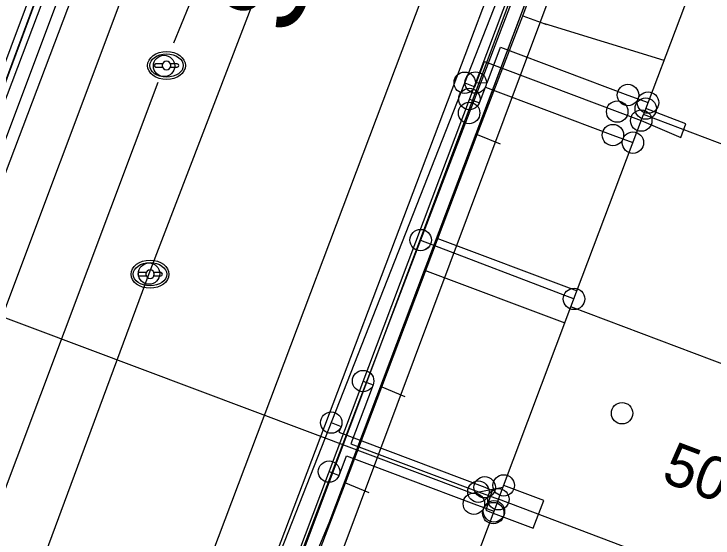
# Model space of a CAD drawing. Extents: x 192672 to 192910, y 446344 to 446512.
# Drawn here: x 192756.71 to 192773.02, y 446443.08 to 446455.32 of the extents above; entities that cross this region are included whole.
import ezdxf

# ---------------------------------------------------------------- set-up
doc = ezdxf.new("R2010")
doc.units = 0
for name, color, linetype in [('B-OI-KL-()_MANTELBUIS_WATER-G', 7, 'Continuous'), ('B-OI-KL-()_OVERIG_RIOOLVRIJVERVAL-S', 7, 'Continuous'), ('B-OI-KL-BUISLEIDING_OLIEGASCHEMICALIEN_GASLAGEDRUK-G', 7, 'Continuous'), ('B-OI-KL-DATA-G', 7, 'Continuous'), ('B-OI-KL-DATA_GTWP-S', 7, 'Continuous'), ('B-OI-KL-DATA_KABELBED-G', 7, 'Continuous'), ('B-OI-KL-DATA_MOF-S', 7, 'Continuous'), ('B-OI-KL-ET_LS-G', 7, 'Continuous'), ('B-OI-KL-ET_LS_DELIVERYPOINT-S', 7, 'Continuous'), ('B-OI-KL-ET_LS_MOF-S', 7, 'Continuous'), ('B-OI-KL-GAS_LD_AFTAKZADEL-S', 7, 'Continuous'), ('B-OI-KL-GAS_LD_DELIVERYPOINT-S', 7, 'Continuous'), ('B-OI-KL-GAS_LD_OVERGANGSSTUK-S', 7, 'Continuous'), ('B-OI-KL-WATER-G', 7, 'Continuous'), ('B-OI-RI-RIOOLVRIJVERVAL-G', 7, 'Continuous'), ('Default', 7, 'Continuous'), ('huisnummerreeks BGT', 7, 'Continuous'), ('inspectie-   rioolput', 7, 'Continuous'), ('kant open verharding', 7, 'Continuous'), ('kant verharding', 7, 'Continuous'), ('pand op maaiveld vlak', 7, 'Continuous'), ('straatnaam', 7, 'Continuous')]:
    doc.layers.add(name, color=color, linetype=linetype)

# ---------------------------------------------------------------- blocks, each defined once
blk = doc.blocks.new('B-OI-KL-GAS_LD_AFTAKZADEL-S')
at = {"layer": 'Default'}
blk.add_circle((0, 0), 0.25, dxfattribs=at)
blk = doc.blocks.new('B-OI-KL-GAS_LD_DELIVERYPOINT-S')
at = {"layer": 'Default'}
blk.add_circle((0, 0), 0.25, dxfattribs=at)
blk = doc.blocks.new('B-OI-KL-GAS_LD_OVERGANGSSTUK-S')
at = {"layer": 'Default'}
blk.add_circle((0, 0), 0.25, dxfattribs=at)
blk = doc.blocks.new('B-OI-KL-ET_LS_DELIVERYPOINT-S')
at = {"layer": 'Default'}
blk.add_circle((0, 0), 0.25, dxfattribs=at)
blk = doc.blocks.new('B-OI-KL-ET_LS_MOF-S')
at = {"layer": 'Default'}
blk.add_circle((0, 0), 0.25, dxfattribs=at)
blk = doc.blocks.new('B-OI-KL-()_OVERIG_RIOOLVRIJVERVAL-S')
at = {"layer": 'Default'}
blk.add_circle((0, 0), 0.25, dxfattribs=at)
blk = doc.blocks.new('B-OI-KL-DATA_GTWP-S')
at = {"layer": 'Default'}
blk.add_circle((0, 0), 0.25, dxfattribs=at)
blk = doc.blocks.new('B-OI-KL-DATA_MOF-S')
at = {"layer": 'Default'}
blk.add_circle((0, 0), 0.25, dxfattribs=at)

msp = doc.modelspace()

# ---------------------------------------------------------------- linework, layer by layer
at = {"layer": 'B-OI-KL-()_MANTELBUIS_WATER-G'}
msp.add_lwpolyline([(192767.826, 446444.213), (192768.121, 446444.271)], dxfattribs=at)
at = {"layer": 'B-OI-KL-BUISLEIDING_OLIEGASCHEMICALIEN_GASLAGEDRUK-G'}
for points in [[(192808.99, 446509.756), (192805.748, 446508.276), (192801.187, 446506.24), (192794.261, 446502.995), (192789.059, 446500.595), (192784.967, 446498.672), (192784.158, 446498.207), (192778.689, 446484.216), (192775.51, 446475.031), (192756.472, 446424.494), (192754.598, 446419.974), (192751.089, 446410.462)], [(192770.261, 446499.113), (192771.393, 446496.803), (192772.556, 446494.554), (192770.877, 446489.886), (192758.67, 446457.345), (192745.084, 446421.436), (192742.217, 446413.618)], [(192767.483, 446453.723), (192767.749, 446453.719), (192768.063, 446454.552), (192771.038, 446453.431)], [(192767.338, 446453.338), (192767.572, 446453.25), (192767.71, 446453.616), (192770.686, 446452.495)], [(192771.038, 446453.431), (192771.506, 446453.255)], [(192770.686, 446452.495), (192771.153, 446452.319)], [(192764.857, 446446.751), (192765.091, 446446.663), (192764.573, 446445.288), (192767.547, 446444.167)], [(192764.061, 446444.637), (192764.295, 446444.549), (192764.467, 446445.007), (192767.441, 446443.886)], [(192767.547, 446444.167), (192768.015, 446443.99)], [(192767.441, 446443.886), (192767.909, 446443.709)]]:
    msp.add_lwpolyline(points, dxfattribs=at)
at = {"layer": 'B-OI-KL-DATA-G'}
for points in [[(192745.236, 446436.264), (192745.276, 446436.371), (192749.491, 446434.791), (192749.794, 446435.599), (192768.74, 446486.807), (192770.369, 446486.306), (192778.924, 446483.081), (192784.343, 446497.176), (192794.941, 446502.078), (192811.396, 446509.756)], [(192757.844, 446425.655), (192756.715, 446426.08), (192759.12, 446432.478), (192750.822, 446435.215), (192749.794, 446435.599), (192768.74, 446486.807), (192770.369, 446486.306), (192778.924, 446483.081), (192784.343, 446497.176), (192794.941, 446502.078), (192811.396, 446509.756)], [(192757.844, 446425.655), (192756.715, 446426.08), (192759.12, 446432.478), (192750.822, 446435.215), (192749.794, 446435.599), (192768.74, 446486.807), (192770.369, 446486.306), (192778.924, 446483.081), (192784.343, 446497.176), (192794.941, 446502.078), (192811.396, 446509.756)], [(192757.844, 446425.655), (192756.715, 446426.08), (192759.12, 446432.478), (192750.822, 446435.215), (192749.794, 446435.599), (192768.74, 446486.807), (192770.369, 446486.306), (192778.924, 446483.081), (192784.343, 446497.176), (192794.941, 446502.078), (192811.396, 446509.756)], [(192757.844, 446425.655), (192756.715, 446426.08), (192759.12, 446432.478), (192750.822, 446435.215), (192749.794, 446435.599), (192768.74, 446486.807), (192770.369, 446486.306), (192778.924, 446483.081), (192784.343, 446497.176), (192794.941, 446502.078), (192811.396, 446509.756)], [(192757.844, 446425.655), (192756.715, 446426.08), (192759.12, 446432.478), (192750.822, 446435.215), (192749.794, 446435.599), (192768.74, 446486.807), (192770.369, 446486.306), (192778.924, 446483.081), (192784.343, 446497.176), (192794.941, 446502.078), (192811.396, 446509.756)], [(192757.844, 446425.655), (192756.715, 446426.08), (192759.12, 446432.478), (192750.822, 446435.215), (192749.794, 446435.599), (192768.74, 446486.807), (192770.369, 446486.306), (192778.924, 446483.081), (192784.343, 446497.176), (192794.941, 446502.078), (192811.396, 446509.756)], [(192757.844, 446425.655), (192756.715, 446426.08), (192759.12, 446432.478), (192750.822, 446435.215), (192749.794, 446435.599), (192768.74, 446486.807), (192770.369, 446486.306), (192778.924, 446483.081), (192784.343, 446497.176), (192794.941, 446502.078), (192811.396, 446509.756)], [(192768.74, 446486.807), (192749.794, 446435.599), (192742.072, 446415.039), (192739.06, 446406.841), (192720.2, 446413.77), (192719.012, 446414.118), (192696.077, 446422.823), (192683.193, 446427.673), (192678.122, 446429.261), (192675.743, 446430.156)], [(192768.74, 446486.807), (192749.794, 446435.599), (192742.072, 446415.039), (192739.06, 446406.841), (192738.917, 446406.249), (192738.75, 446405.758), (192738.438, 446405.088), (192738.002, 446404.406), (192737.543, 446403.858), (192737.067, 446403.408), (192736.56, 446403.025), (192736.06, 446402.723), (192733.684, 446396.245), (192734.518, 446394.712), (192730.316, 446383.423), (192727.316, 446375.697), (192722.899, 446364.033), (192722.458, 446362.715), (192718.077, 446351.086), (192716.68, 446347.404), (192715.968, 446345.556)], [(192768.74, 446486.807), (192749.794, 446435.599), (192742.072, 446415.039), (192739.06, 446406.841), (192738.917, 446406.249), (192738.75, 446405.758), (192738.438, 446405.088), (192738.002, 446404.406), (192737.543, 446403.858), (192737.067, 446403.408), (192736.56, 446403.025), (192736.06, 446402.723), (192733.684, 446396.245), (192734.518, 446394.712), (192730.316, 446383.423), (192727.316, 446375.697), (192722.899, 446364.033), (192722.458, 446362.715), (192718.077, 446351.086), (192716.68, 446347.404), (192715.968, 446345.556)], [(192768.74, 446486.807), (192749.794, 446435.599), (192742.072, 446415.039), (192739.06, 446406.841), (192738.917, 446406.249), (192738.75, 446405.758), (192738.438, 446405.088), (192738.002, 446404.406), (192737.543, 446403.858), (192737.067, 446403.408), (192736.56, 446403.025), (192736.06, 446402.723), (192733.684, 446396.245), (192734.518, 446394.712), (192730.316, 446383.423), (192727.316, 446375.697), (192722.899, 446364.033), (192722.458, 446362.715), (192718.077, 446351.086), (192716.68, 446347.404), (192715.968, 446345.556)], [(192768.74, 446486.807), (192749.794, 446435.599), (192742.072, 446415.039), (192739.06, 446406.841), (192738.917, 446406.249), (192738.75, 446405.758), (192738.438, 446405.088), (192738.002, 446404.406), (192737.543, 446403.858), (192737.067, 446403.408), (192736.56, 446403.025), (192736.06, 446402.723), (192733.684, 446396.245), (192734.518, 446394.712), (192730.316, 446383.423), (192727.316, 446375.697), (192722.899, 446364.033), (192722.458, 446362.715), (192718.077, 446351.086), (192716.68, 446347.404), (192715.968, 446345.556)], [(192768.74, 446486.807), (192749.794, 446435.599), (192742.072, 446415.039), (192739.06, 446406.841), (192738.917, 446406.249), (192738.75, 446405.758), (192738.438, 446405.088), (192738.002, 446404.406), (192737.543, 446403.858), (192737.067, 446403.408), (192736.56, 446403.025), (192736.06, 446402.723), (192733.684, 446396.245), (192734.518, 446394.712), (192730.316, 446383.423), (192727.316, 446375.697), (192722.899, 446364.033), (192722.458, 446362.715), (192718.077, 446351.086), (192716.68, 446347.404), (192715.968, 446345.556)], [(192768.74, 446486.807), (192749.794, 446435.599), (192742.072, 446415.039), (192739.06, 446406.841), (192738.917, 446406.249), (192738.75, 446405.758), (192738.438, 446405.088), (192738.002, 446404.406), (192737.543, 446403.858), (192737.067, 446403.408), (192736.56, 446403.025), (192736.06, 446402.723), (192733.684, 446396.245), (192734.518, 446394.712), (192730.316, 446383.423), (192727.316, 446375.697), (192722.899, 446364.033), (192722.458, 446362.715), (192718.077, 446351.086), (192716.68, 446347.404), (192715.968, 446345.556)], [(192768.74, 446486.807), (192749.794, 446435.599), (192742.072, 446415.039), (192739.06, 446406.841), (192738.917, 446406.249), (192738.75, 446405.758), (192738.438, 446405.088), (192738.002, 446404.406), (192737.543, 446403.858), (192737.067, 446403.408), (192736.56, 446403.025), (192736.06, 446402.723), (192733.684, 446396.245), (192734.518, 446394.712), (192730.316, 446383.423), (192727.316, 446375.697), (192722.899, 446364.033), (192722.458, 446362.715), (192718.077, 446351.086), (192716.68, 446347.404), (192715.968, 446345.556)], [(192768.74, 446486.807), (192749.794, 446435.599), (192742.072, 446415.039), (192739.06, 446406.841), (192738.917, 446406.249), (192738.75, 446405.758), (192738.438, 446405.088), (192738.002, 446404.406), (192737.543, 446403.858), (192737.067, 446403.408), (192736.56, 446403.025), (192736.06, 446402.723), (192733.684, 446396.245), (192734.518, 446394.712), (192730.316, 446383.423), (192727.316, 446375.697), (192722.899, 446364.033), (192722.458, 446362.715), (192718.077, 446351.086), (192716.68, 446347.404), (192715.968, 446345.556)], [(192768.74, 446486.807), (192749.794, 446435.599), (192742.072, 446415.039), (192739.06, 446406.841), (192738.917, 446406.249), (192738.75, 446405.758), (192738.438, 446405.088), (192738.002, 446404.406), (192737.543, 446403.858), (192737.067, 446403.408), (192736.56, 446403.025), (192736.06, 446402.723), (192733.684, 446396.245), (192734.518, 446394.712), (192730.316, 446383.423), (192727.316, 446375.697), (192722.899, 446364.033), (192722.458, 446362.715), (192718.077, 446351.086), (192716.68, 446347.404), (192715.968, 446345.556)], [(192768.74, 446486.807), (192749.794, 446435.599), (192742.072, 446415.039), (192739.06, 446406.841), (192738.917, 446406.249), (192738.75, 446405.758), (192738.438, 446405.088), (192738.002, 446404.406), (192737.543, 446403.858), (192737.067, 446403.408), (192736.56, 446403.025), (192736.06, 446402.723), (192733.684, 446396.245), (192734.518, 446394.712), (192730.316, 446383.423), (192727.316, 446375.697), (192722.899, 446364.033), (192722.458, 446362.715), (192718.077, 446351.086), (192716.68, 446347.404), (192715.968, 446345.556)], [(192768.74, 446486.807), (192749.794, 446435.599), (192742.072, 446415.039), (192739.06, 446406.841), (192738.917, 446406.249), (192738.75, 446405.758), (192738.438, 446405.088), (192738.002, 446404.406), (192737.543, 446403.858), (192737.067, 446403.408), (192736.56, 446403.025), (192736.06, 446402.723), (192733.684, 446396.245), (192734.518, 446394.712), (192730.316, 446383.423), (192727.316, 446375.697), (192722.899, 446364.033), (192722.458, 446362.715), (192718.077, 446351.086), (192716.68, 446347.404), (192715.968, 446345.556)], [(192768.74, 446486.807), (192749.794, 446435.599), (192742.072, 446415.039), (192739.06, 446406.841), (192738.917, 446406.249), (192738.75, 446405.758), (192738.438, 446405.088), (192738.002, 446404.406), (192737.543, 446403.858), (192737.067, 446403.408), (192736.56, 446403.025), (192736.06, 446402.723), (192733.684, 446396.245), (192734.518, 446394.712), (192730.316, 446383.423), (192727.316, 446375.697), (192722.899, 446364.033), (192722.458, 446362.715), (192718.077, 446351.086), (192716.68, 446347.404), (192715.968, 446345.556)], [(192768.74, 446486.807), (192749.794, 446435.599), (192742.072, 446415.039), (192739.06, 446406.841), (192738.917, 446406.249), (192738.75, 446405.758), (192738.438, 446405.088), (192738.002, 446404.406), (192737.543, 446403.858), (192737.067, 446403.408), (192736.56, 446403.025), (192736.06, 446402.723), (192733.684, 446396.245), (192734.518, 446394.712), (192730.316, 446383.423), (192727.316, 446375.697), (192722.899, 446364.033), (192722.458, 446362.715), (192718.077, 446351.086), (192716.68, 446347.404), (192715.968, 446345.556)], [(192768.74, 446486.807), (192749.794, 446435.599), (192742.072, 446415.039), (192739.06, 446406.841), (192738.917, 446406.249), (192738.75, 446405.758), (192738.438, 446405.088), (192738.002, 446404.406), (192737.543, 446403.858), (192737.067, 446403.408), (192736.56, 446403.025), (192736.06, 446402.723), (192733.684, 446396.245), (192734.518, 446394.712), (192730.316, 446383.423), (192727.316, 446375.697), (192722.899, 446364.033), (192722.458, 446362.715), (192718.077, 446351.086), (192716.68, 446347.404), (192715.968, 446345.556)], [(192768.74, 446486.807), (192749.794, 446435.599), (192742.072, 446415.039), (192739.06, 446406.841), (192738.917, 446406.249), (192738.75, 446405.758), (192738.438, 446405.088), (192738.002, 446404.406), (192737.543, 446403.858), (192737.067, 446403.408), (192736.56, 446403.025), (192736.06, 446402.723), (192733.684, 446396.245), (192734.518, 446394.712), (192730.316, 446383.423), (192727.316, 446375.697), (192722.899, 446364.033), (192722.458, 446362.715), (192718.077, 446351.086), (192716.68, 446347.404), (192715.968, 446345.556)], [(192733.785, 446392.743), (192734.518, 446394.712), (192733.684, 446396.245), (192736.06, 446402.723), (192736.56, 446403.025), (192737.067, 446403.408), (192737.543, 446403.858), (192738.002, 446404.406), (192738.438, 446405.088), (192738.75, 446405.758), (192738.917, 446406.249), (192739.06, 446406.841), (192742.072, 446415.039), (192749.794, 446435.599), (192768.74, 446486.807)], [(192768.74, 446486.807), (192749.794, 446435.599), (192749.491, 446434.791), (192745.276, 446436.371), (192745.236, 446436.264)], [(192757.844, 446425.655), (192756.715, 446426.08), (192759.12, 446432.478), (192750.822, 446435.215), (192749.794, 446435.599), (192768.74, 446486.807)], [(192757.844, 446425.655), (192757.559, 446425.762), (192762.265, 446439.137), (192764.067, 446443.44), (192769.642, 446458.233), (192775.813, 446474.194), (192776.451, 446473.954)], [(192757.844, 446425.655), (192757.559, 446425.762), (192762.265, 446439.137), (192764.067, 446443.44), (192769.642, 446458.233), (192774.396, 446470.528), (192775.064, 446470.277)], [(192745.236, 446436.264), (192745.276, 446436.371), (192749.491, 446434.791), (192749.794, 446435.599), (192760.694, 446465.06)], [(192768.581, 446455.281), (192770.176, 446459.553), (192771.392, 446462.778)], [(192745.236, 446436.264), (192745.276, 446436.371), (192749.491, 446434.791), (192749.794, 446435.599), (192759.161, 446460.917)], [(192757.844, 446425.655), (192757.559, 446425.762), (192762.265, 446439.137), (192764.067, 446443.44), (192769.642, 446458.233), (192770.479, 446460.397), (192771.235, 446460.112)], [(192757.844, 446425.655), (192757.559, 446425.762), (192762.265, 446439.137), (192764.067, 446443.44), (192769.642, 446458.233), (192772.918, 446456.997)], [(192745.236, 446436.264), (192745.276, 446436.371), (192749.491, 446434.791), (192749.794, 446435.599), (192757.561, 446456.593)], [(192767.516, 446452.511), (192768.581, 446455.281)], [(192768.581, 446455.281), (192769.097, 446455.091)], [(192771.88, 446454.24), (192769.097, 446455.091)], [(192769.097, 446455.091), (192769.126, 446455.08)], [(192765.29, 446446.613), (192767.516, 446452.511)], [(192767.516, 446452.511), (192768.054, 446452.292)], [(192757.844, 446425.655), (192757.559, 446425.762), (192762.265, 446439.137), (192764.067, 446443.44), (192766.573, 446450.09), (192769.849, 446448.856)], [(192757.844, 446425.655), (192757.559, 446425.762), (192762.265, 446439.137), (192764.067, 446443.44), (192766.291, 446449.342), (192769.567, 446448.108)], [(192764.443, 446444.377), (192765.29, 446446.613)], [(192765.29, 446446.613), (192765.828, 446446.389)], [(192761.261, 446436.309), (192762.488, 446439.513), (192763.052, 446440.678), (192763.221, 446441.171), (192764.443, 446444.377)], [(192764.443, 446444.377), (192764.988, 446444.146)]]:
    msp.add_lwpolyline(points, dxfattribs=at)
at = {"layer": 'B-OI-KL-DATA_KABELBED-G'}
for points in [[(192781.5, 446489.931), (192778.594, 446482.476), (192777.525, 446479.682), (192775.942, 446475.544), (192774.287, 446471.219), (192774.071, 446470.654), (192771.264, 446463.317), (192769.537, 446458.803), (192769.421, 446458.498), (192766.199, 446450.043), (192761.064, 446436.566), (192759.105, 446431.427), (192758.318, 446429.36), (192752.08, 446412.145), (192751.738, 446411.209)], [(192741.713, 446414.036), (192744.844, 446423.02), (192745.937, 446425.921), (192747.211, 446429.306), (192749.226, 446434.655), (192749.571, 446435.71), (192751.005, 446439.535), (192753.868, 446447.173), (192756.275, 446453.596), (192757.334, 446456.42), (192758.244, 446458.849)], [(192766.573, 446450.09), (192769.642, 446458.233)], [(192755.845, 446451.955), (192757.561, 446456.593)], [(192766.199, 446450.043), (192769.779, 446448.67)], [(192766.291, 446449.342), (192766.573, 446450.09)], [(192766.573, 446450.09), (192769.849, 446448.856)], [(192762.662, 446440.084), (192764.067, 446443.44), (192766.291, 446449.342)], [(192766.291, 446449.342), (192769.567, 446448.108)]]:
    msp.add_lwpolyline(points, dxfattribs=at)
at = {"layer": 'B-OI-KL-ET_LS-G'}
for points in [[(192737.952, 446406.43), (192738.358, 446406.675), (192738.717, 446406.983), (192739.022, 446407.347), (192739.262, 446407.755), (192739.381, 446408.001), (192760.347, 446463.479), (192768.676, 446485.881)], [(192751.683, 446410.693), (192751.297, 446411.193), (192751.249, 446411.263), (192751.183, 446411.41), (192751.151, 446411.568), (192751.154, 446411.72), (192751.195, 446411.884), (192761.82, 446439.945), (192769.713, 446460.045), (192776.093, 446476.975), (192777.923, 446482.086)], [(192769.108, 446460.374), (192769.235, 446460.249), (192769.933, 446460.043), (192761.858, 446438.501), (192761.067, 446436.302), (192760.076, 446436.613), (192759.938, 446436.632)], [(192767.228, 446453.717), (192767.461, 446453.626), (192767.691, 446454.212), (192770.786, 446453.045)], [(192771.347, 446452.834), (192772.272, 446452.439), (192772.389, 446452.761), (192771.453, 446453.114)], [(192770.786, 446453.045), (192771.347, 446452.834)], [(192764.112, 446445.781), (192764.345, 446445.69), (192764.291, 446445.554), (192767.694, 446444.271)], [(192767.893, 446443.667), (192768.829, 446443.314), (192769.073, 446443.961), (192768.137, 446444.313)], [(192767.694, 446444.271), (192767.867, 446444.197), (192767.72, 446443.732), (192767.893, 446443.667)]]:
    msp.add_lwpolyline(points, dxfattribs=at)
at = {"layer": 'B-OI-KL-WATER-G'}
msp.add_lwpolyline([(192754.259, 446449.069), (192754.494, 446448.983), (192767.404, 446444.129), (192768.121, 446444.271)], dxfattribs=at)
at = {"layer": 'B-OI-RI-RIOOLVRIJVERVAL-G'}
for points in [[(192759.86, 446449.26), (192779.05, 446499.28)], [(192760.441, 446454.647), (192761.511, 446457.277)], [(192760.065, 446453.723), (192752.396, 446433.312), (192756.051, 446431.824), (192756.134, 446431.668), (192755.956, 446431.084), (192756.039, 446430.928), (192756.54, 446430.74)], [(192740.63, 446397.31), (192759.86, 446449.26)]]:
    msp.add_lwpolyline(points, dxfattribs=at)
at = {"layer": 'inspectie-   rioolput'}
for p, q in [((192760.175, 446454.158), (192760.018, 446454.158)), ((192760.018, 446454.083), (192760.175, 446454.083)), ((192760.518, 446454.158), (192760.361, 446454.158)), ((192760.361, 446454.083), (192760.518, 446454.083)), ((192759.79, 446449.284), (192759.633, 446449.284)), ((192759.633, 446449.209), (192759.79, 446449.209)), ((192760.133, 446449.284), (192759.976, 446449.284)), ((192759.976, 446449.209), (192760.133, 446449.209))]:
    msp.add_line(p, q, dxfattribs=at)
for centre, radius, start, end in [((192760.018, 446454.12), 0.0375, 90, 270), ((192760.268, 446454.12), 0.1, 0, 180), ((192760.268, 446454.12), 0.1, 157.9757, 180), ((192760.268, 446454.12), 0.1, 180, 202.0243), ((192760.268, 446454.12), 0.1, 180, 0), ((192760.268, 446454.12), 0.1, 0, 22.0243), ((192760.268, 446454.12), 0.1, 337.9757, 0), ((192760.518, 446454.12), 0.0375, 270, 90), ((192759.633, 446449.246), 0.0375, 90, 270), ((192759.883, 446449.246), 0.1, 0, 180), ((192759.883, 446449.246), 0.1, 157.9757, 180), ((192759.883, 446449.246), 0.1, 180, 202.0243), ((192759.883, 446449.246), 0.1, 180, 0), ((192759.883, 446449.246), 0.1, 0, 22.0243), ((192759.883, 446449.246), 0.1, 337.9757, 0), ((192760.133, 446449.246), 0.0375, 270, 90)]:
    msp.add_arc(centre, radius, start, end, dxfattribs=at)
for centre, major_axis, ratio in [((192760.268, 446454.12), (-0.442, 0), 0.73911), ((192760.268, 446454.12), (-0.392, 0), 0.689655), ((192759.883, 446449.246), (-0.442, 0), 0.73911), ((192759.883, 446449.246), (-0.392, 0), 0.689655)]:
    msp.add_ellipse(centre, major_axis=major_axis, ratio=ratio, dxfattribs=at)
at = {"layer": 'kant open verharding'}
msp.add_lwpolyline([(192763.131, 446439.452), (192770.245, 446458.483), (192770.698, 446459.694), (192771.023, 446459.551)], dxfattribs=at)
at = {"layer": 'kant verharding'}
for p, q in [((192759.42, 446437.63), (192767.733, 446459.699)), ((192751.413, 446438.852), (192759.133, 446459.368)), ((192760.585, 446459.343), (192752.554, 446437.93))]:
    msp.add_line(p, q, dxfattribs=at)
msp.add_lwpolyline([(192768.035, 446459.06), (192768.878, 446458.723), (192760.872, 446437.554), (192760.052, 446437.884)], dxfattribs=at)
at = {"layer": 'pand op maaiveld vlak'}
for p, q in [((192769.708, 446448.482), (192771.4, 446452.974)), ((192782.591, 446448.755), (192771.4, 446452.974)), ((192768.015, 446443.99), (192769.708, 446448.482)), ((192780.892, 446444.248), (192769.708, 446448.482)), ((192779.205, 446439.772), (192768.015, 446443.99))]:
    msp.add_line(p, q, dxfattribs=at)
for points in [[(192782.591, 446448.755), (192784.284, 446453.247), (192780.202, 446454.786), (192773.094, 446457.465), (192771.4, 446452.974)], [(192768.015, 446443.99), (192766.321, 446439.499), (192773.437, 446436.816), (192777.512, 446435.28), (192779.205, 446439.772)]]:
    msp.add_lwpolyline(points, dxfattribs=at)

# ---------------------------------------------------------------- block references
at = {"layer": 'B-OI-KL-()_OVERIG_RIOOLVRIJVERVAL-S'}
for p in [(192760.21, 446454.11), (192759.86, 446449.26)]:
    msp.add_blockref('B-OI-KL-()_OVERIG_RIOOLVRIJVERVAL-S', p, dxfattribs=at)
at = {"layer": 'B-OI-KL-DATA_GTWP-S'}
for p in [(192766.199, 446450.042), (192769.779, 446448.67)]:
    msp.add_blockref('B-OI-KL-DATA_GTWP-S', p, dxfattribs=at)
at = {"layer": 'B-OI-KL-DATA_MOF-S'}
for p in [(192767.331, 446453.012), (192766.199, 446450.043), (192770.9, 446446)]:
    msp.add_blockref('B-OI-KL-DATA_MOF-S', p, dxfattribs=at)
at = {"layer": 'B-OI-KL-ET_LS_DELIVERYPOINT-S'}
for p in [(192771.453, 446453.114), (192771.347, 446452.834), (192768.137, 446444.313), (192767.893, 446443.667)]:
    msp.add_blockref('B-OI-KL-ET_LS_DELIVERYPOINT-S', p, dxfattribs=at)
at = {"layer": 'B-OI-KL-ET_LS_MOF-S'}
for p in [(192767.228, 446453.717), (192770.786, 446453.045), (192764.112, 446445.781), (192767.694, 446444.271)]:
    msp.add_blockref('B-OI-KL-ET_LS_MOF-S', p, dxfattribs=at)
at = {"layer": 'B-OI-KL-GAS_LD_AFTAKZADEL-S'}
for p in [(192767.483, 446453.723), (192767.338, 446453.338), (192764.857, 446446.751), (192764.061, 446444.637)]:
    msp.add_blockref('B-OI-KL-GAS_LD_AFTAKZADEL-S', p, dxfattribs=at)
at = {"layer": 'B-OI-KL-GAS_LD_DELIVERYPOINT-S'}
for p in [(192771.506, 446453.255), (192771.153, 446452.319), (192768.015, 446443.99), (192767.909, 446443.709)]:
    msp.add_blockref('B-OI-KL-GAS_LD_DELIVERYPOINT-S', p, dxfattribs=at)
at = {"layer": 'B-OI-KL-GAS_LD_OVERGANGSSTUK-S'}
for p in [(192771.038, 446453.431), (192770.686, 446452.495), (192767.547, 446444.167), (192767.441, 446443.886)]:
    msp.add_blockref('B-OI-KL-GAS_LD_OVERGANGSSTUK-S', p, dxfattribs=at)

# ---------------------------------------------------------------- texts
at = {"layer": 'huisnummerreeks BGT'}
msp.add_text('50', height=1, rotation=339.4, dxfattribs=at).set_placement((192771.787, 446444.421))
at = {"layer": 'straatnaam'}
msp.add_text('Sperwerstraat', height=2, rotation=71, dxfattribs=at).set_placement((192763.228, 446454.747))

doc.saveas('drawing.dxf')
